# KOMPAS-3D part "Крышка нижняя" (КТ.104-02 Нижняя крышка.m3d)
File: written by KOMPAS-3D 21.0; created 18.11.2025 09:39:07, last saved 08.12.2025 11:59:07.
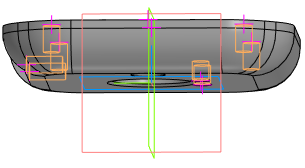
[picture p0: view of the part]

Document properties: Автор: User; Полное имя файла: C:\Users\User\Desktop\Pelorus PRO доработки\Крышка нижняя\КТ.104-02 Нижняя крышка.m3d

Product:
- Part/product: Крышка нижняя
    Материал: АМг6  ГОСТ 4784-2019 (density 2650 kg/m3)
    Масса: 0.379842
  - Body: Тело 1
      Масса: 0.373615

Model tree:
1. Эскиз:1
2. Элемент выдавливания:1
     Расстояние 1 = 18
3. Эскиз:2  (with: Элемент выдавливания:1)
4. Элемент выдавливания:2
     Расстояние 2 = 18
5. Эскиз:3  (with: Элемент выдавливания:1, Элемент выдавливания:2)
6. Элемент выдавливания:3
     Расстояние 1 = 2
7. Эскиз:4  (with: Элемент выдавливания:3)
8. Отверстие:1  (with: Элемент выдавливания:3)
     Глубина выреза = 40; Диаметр отверстия = 10.5; Угол конуса дна = 118; Расстояние 2 = -32; Диаметр цековки = 28; Глубина цековки = 8
9. Скругление:3  (with: Элемент выдавливания:2)
     Радиус = 23
10. Скругление:4  (with: Скругление:3, Элемент выдавливания:1, Элемент выдавливания:2)
     Радиус = 15
11. Эскиз:5  (with: Элемент выдавливания:1, Отверстие:2, Скругление:4)
12. Элемент выдавливания:4
     Расстояние 2 = 13.2
13. Эскиз:6  (with: Элемент выдавливания:4, Скругление:4)
14. Отверстие:3  (with: Элемент выдавливания:4)  (labels: M6)
     Глубина выреза = 15; Диаметр отверстия = 4.91747; Угол конуса дна = 118; Расстояние 1 = 3.7665; Расстояние 2 = 44
15. M6  (with: Элемент выдавливания:4)  (labels: M6; cil0_24705-2004 coarse)
     Длина резьбы = 13; Шаг резьбы = 1; Номинальный диаметр резьбы = 6
16. Отверстие:4  (with: Элемент выдавливания:4, M6)  (labels: M6; cil0_24705-2004 coarse)
     Глубина выреза = 15; Диаметр отверстия = 4.91747; Угол конуса дна = 118; Расстояние 1 = 3.7665; Расстояние 2 = 17; Длина резьбы = 13; Шаг резьбы = 1; Номинальный диаметр резьбы = 6
17. Отверстие:5  (with: Элемент выдавливания:1, Скругление:4)
     Глубина выреза = 40; Диаметр отверстия = 18; Угол конуса дна = 118; Расстояние 1 = 37.5; Расстояние 2 = 37.5; Диаметр цековки = 30; Глубина цековки = 10
18. Эскиз:8  (with: Элемент выдавливания:1, Элемент выдавливания:3)
19. Отверстие:6  (with: Элемент выдавливания:1, M6)  (labels: M6; cil0_24705-2004 coarse)
     Глубина выреза = 12; Диаметр отверстия = 4.91747; Угол конуса дна = 118; Расстояние 1 = 87.1482; Расстояние 2 = 87.1482; Диаметр зенковки = 7; Глубина зенковки = 1.04127; Угол зенковки = 90; Длина резьбы = 10; Шаг резьбы = 1; Номинальный диаметр резьбы = 6
20. Массив по точкам:1
21. Экземпляр ( 3 )  (with: Отверстие:6, Эскиз:8)  (labels: M6)
22. Экземпляр ( 1 )  (with: Отверстие:6, Эскиз:8)  (labels: M6)
23. Экземпляр ( 2 )  (with: Отверстие:6, Эскиз:8)  (labels: M6)
24. Эскиз:13  (with: Элемент выдавливания:3, Элемент выдавливания:6)
25. Элемент выдавливания:7  (with: Отверстие:1)
     Расстояние 2 = 8
26. Скругление:5  (with: Отверстие:1, Элемент выдавливания:7)
     Радиус = 2
27. Фаска:1  (with: Отверстие:5, Элемент выдавливания:3, Элемент выдавливания:7, Отверстие:1)
     Угол = 45; Длина 1 = 1; Длина 2 = 1
28. Эскиз:14  (with: Элемент выдавливания:1)
29. Отверстие:7  (with: Элемент выдавливания:1, Скругление:4, M6)  (labels: M6; cil0_24705-2004 coarse)
     Глубина выреза = 8; Диаметр отверстия = 4.91747; Угол конуса дна = 118; Расстояние 1 = 29.5; Расстояние 2 = 55.5; Диаметр зенковки = 7; Глубина зенковки = 1.04127; Угол зенковки = 90; Длина резьбы = 7; Шаг резьбы = 1; Номинальный диаметр резьбы = 6
30. Массив по точкам:2  (with: Экземпляр ( 1 ), Отверстие:7, Эскиз:14)  (labels: M6)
